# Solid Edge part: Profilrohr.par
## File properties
Username: bmolnar
Dokumentum tartalom típus: 0
Author: bmolnar
Last saved by: bmolnar
Revision: 79
Sűrűség: 0,000 kg/m^3
Pontosság: 0,990
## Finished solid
Body 1: solid body, 115 faces, 338 edges, 224 vertices.
  Faces by surface: cylinder 59, plane 56
  Edges by curve: line 220, circle 118
Bounding box of the edges (mm): 77.000 x 77.000 x 41.500, from (-38.5, -38.5, -5) to (38.5, 38.5, 36.5).
Cylindrical faces by radius (mm): R0.15 x24, R0.25 x24, R1 x4, R12 x4, R13.5 x2, R31.5 x1
Planar faces by outward normal: +x 13, +y 14, +z 1, -x 13, -y 14, -z 1
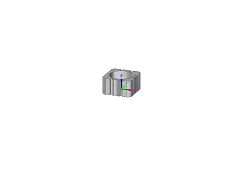
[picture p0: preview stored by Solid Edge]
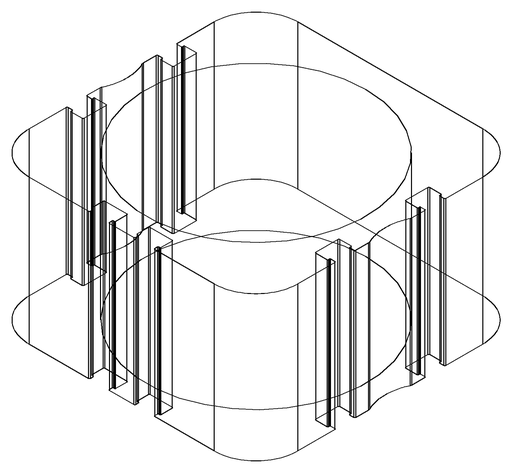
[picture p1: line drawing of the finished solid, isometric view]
